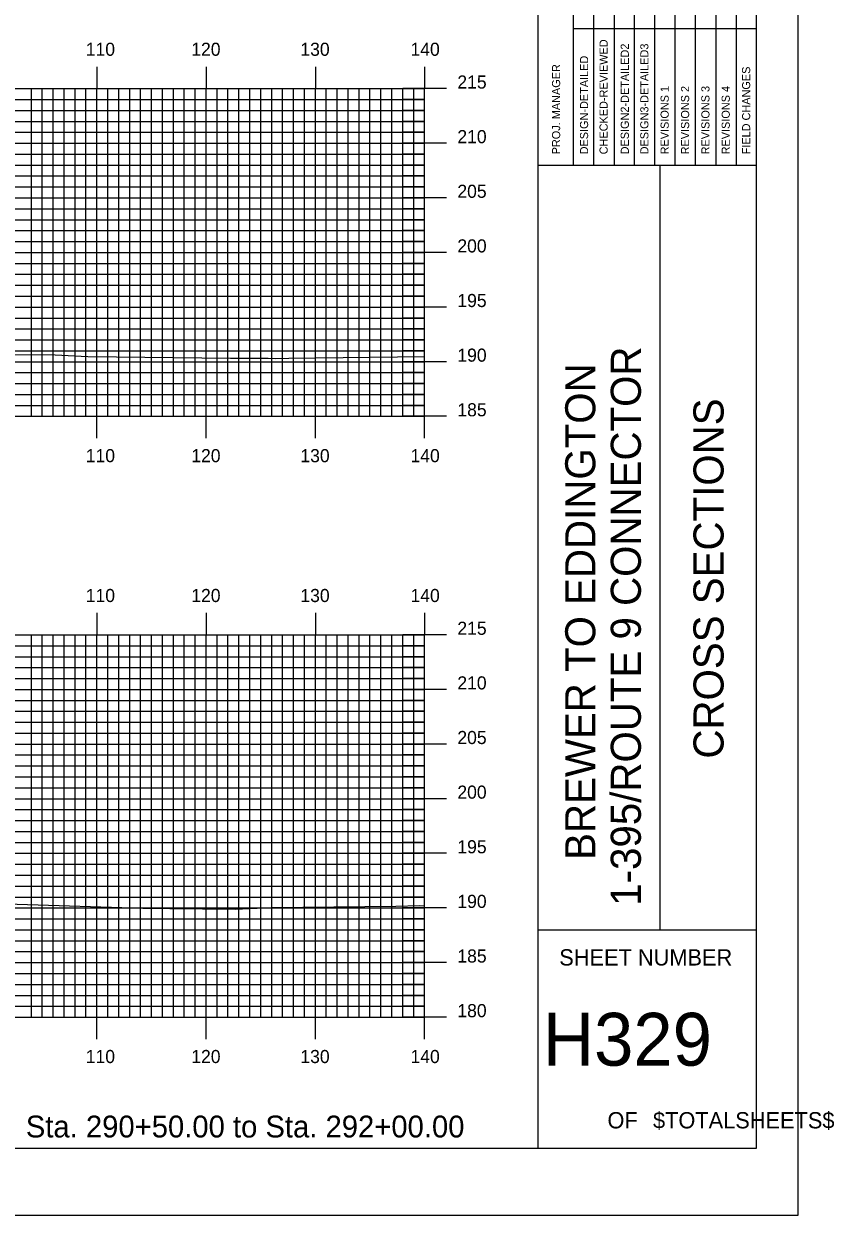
# Model space of a CAD drawing. Extents: x 1813735 to 1814078, y 442591 to 442811.
# Drawn here: x 1814003.8 to 1814078, y 442590.5 to 442699.6 of the extents above; entities that cross this region are included whole.
import ezdxf

# ---------------------------------------------------------------- set-up
doc = ezdxf.new("R2010")
doc.units = 0
for name, color, linetype in [('BORDER', 7, 'Continuous'), ('H_V ANNOTATION', 7, 'Continuous'), ('MAJOR', 7, 'Continuous'), ('MINOR', 7, 'Continuous'), ('PLOT BOUNDARY', 7, 'Continuous'), ('S_Roadway_Centerline', 7, 'Continuous')]:
    doc.layers.add(name, color=color, linetype=linetype)

msp = doc.modelspace()

# ---------------------------------------------------------------- linework, layer by layer
at = {"layer": 'BORDER'}
for p, q in [((1814050.88, 442596.67), (1814050.88, 442806.67)), ((1814050.88, 442686.67), (1814070.88, 442686.67)), ((1814062.06, 442616.67), (1814062.06, 442686.67)), ((1814050.88, 442616.67), (1814070.88, 442616.67))]:
    msp.add_line(p, q, dxfattribs=at)
msp.add_lwpolyline([(1813750.88, 442596.67), (1814070.88, 442596.67), (1814070.88, 442806.67), (1813750.88, 442806.67)], close=True, dxfattribs=at)
for points in [[(1814055.98, 442686.68), (1814055.98, 442721.67)], [(1814057.84, 442721.67), (1814057.84, 442686.68)], [(1814059.7, 442686.68), (1814059.7, 442721.67)], [(1814061.57, 442686.68), (1814061.57, 442721.67)], [(1814063.43, 442686.68), (1814063.43, 442721.67)], [(1814065.29, 442686.68), (1814065.29, 442721.67)], [(1814067.16, 442686.68), (1814067.16, 442721.67)], [(1814069.02, 442686.68), (1814069.02, 442721.67)], [(1814054.11, 442686.68), (1814054.11, 442720.26)], [(1814054.11, 442699.17), (1814070.88, 442699.17)]]:
    msp.add_lwpolyline(points, dxfattribs=at)
at = {"layer": 'MAJOR'}
for p, q in [((1814010.48, 442695.67), (1814010.48, 442693.67)), ((1814020.48, 442695.67), (1814020.48, 442693.67)), ((1814030.48, 442695.67), (1814030.48, 442693.67)), ((1814040.48, 442695.67), (1814040.48, 442693.67)), ((1813760.48, 442693.67), (1814040.48, 442693.67)), ((1813760.48, 442693.67), (1814040.48, 442693.67)), ((1814010.48, 442663.67), (1814010.48, 442693.67)), ((1814020.48, 442663.67), (1814020.48, 442693.67)), ((1814030.48, 442663.67), (1814030.48, 442693.67)), ((1814042.49, 442693.67), (1814038.48, 442693.67)), ((1814040.48, 442663.67), (1814040.48, 442693.67)), ((1814040.48, 442663.67), (1814040.48, 442693.67)), ((1813760.48, 442688.67), (1814040.48, 442688.67)), ((1814042.49, 442688.67), (1814038.48, 442688.67)), ((1813760.48, 442683.67), (1814040.48, 442683.67)), ((1814042.49, 442683.67), (1814038.48, 442683.67)), ((1813760.48, 442678.67), (1814040.48, 442678.67)), ((1814042.49, 442678.67), (1814038.48, 442678.67)), ((1813760.48, 442673.67), (1814040.48, 442673.67)), ((1814042.49, 442673.67), (1814038.48, 442673.67)), ((1813760.48, 442668.67), (1814040.48, 442668.67)), ((1814042.49, 442668.67), (1814038.48, 442668.67)), ((1813760.48, 442663.67), (1814040.48, 442663.67)), ((1813760.48, 442663.67), (1814040.48, 442663.67)), ((1814010.48, 442661.66), (1814010.48, 442663.67)), ((1814020.48, 442661.66), (1814020.48, 442663.67)), ((1814030.48, 442661.66), (1814030.48, 442663.67)), ((1814042.49, 442663.67), (1814038.48, 442663.67)), ((1814040.48, 442661.66), (1814040.48, 442663.67)), ((1814010.48, 442645.67), (1814010.48, 442643.67)), ((1814020.48, 442645.67), (1814020.48, 442643.67)), ((1814030.48, 442645.67), (1814030.48, 442643.67)), ((1814040.48, 442645.67), (1814040.48, 442643.67)), ((1813760.48, 442643.67), (1814040.48, 442643.67)), ((1813760.48, 442643.67), (1814040.48, 442643.67)), ((1814010.48, 442608.67), (1814010.48, 442643.67)), ((1814020.48, 442608.67), (1814020.48, 442643.67)), ((1814030.48, 442608.67), (1814030.48, 442643.67)), ((1814042.49, 442643.67), (1814038.48, 442643.67)), ((1814040.48, 442608.67), (1814040.48, 442643.67)), ((1814040.48, 442608.67), (1814040.48, 442643.67)), ((1813760.48, 442638.67), (1814040.48, 442638.67)), ((1814042.49, 442638.67), (1814038.48, 442638.67)), ((1813760.48, 442633.67), (1814040.48, 442633.67)), ((1814042.49, 442633.67), (1814038.48, 442633.67)), ((1813760.48, 442628.67), (1814040.48, 442628.67)), ((1814042.49, 442628.67), (1814038.48, 442628.67)), ((1813760.48, 442623.67), (1814040.48, 442623.67)), ((1814042.49, 442623.67), (1814038.48, 442623.67)), ((1813760.48, 442618.67), (1814040.48, 442618.67)), ((1814042.49, 442618.67), (1814038.48, 442618.67)), ((1813760.48, 442613.67), (1814040.48, 442613.67)), ((1814042.49, 442613.67), (1814038.48, 442613.67)), ((1813760.48, 442608.67), (1814040.48, 442608.67)), ((1813760.48, 442608.67), (1814040.48, 442608.67)), ((1814010.48, 442606.66), (1814010.48, 442608.67)), ((1814020.48, 442606.66), (1814020.48, 442608.67)), ((1814030.48, 442606.66), (1814030.48, 442608.67)), ((1814042.49, 442608.67), (1814038.48, 442608.67)), ((1814040.48, 442606.66), (1814040.48, 442608.67))]:
    msp.add_line(p, q, dxfattribs=at)
at = {"layer": 'MINOR'}
for p, q in [((1814004.48, 442663.67), (1814004.48, 442693.67)), ((1814005.48, 442663.67), (1814005.48, 442693.67)), ((1814006.48, 442663.67), (1814006.48, 442693.67)), ((1814007.48, 442663.67), (1814007.48, 442693.67)), ((1814008.48, 442663.67), (1814008.48, 442693.67)), ((1814009.48, 442663.67), (1814009.48, 442693.67)), ((1814011.48, 442663.67), (1814011.48, 442693.67)), ((1814012.48, 442663.67), (1814012.48, 442693.67)), ((1814013.48, 442663.67), (1814013.48, 442693.67)), ((1814014.48, 442663.67), (1814014.48, 442693.67)), ((1814015.48, 442663.67), (1814015.48, 442693.67)), ((1814016.48, 442663.67), (1814016.48, 442693.67)), ((1814017.48, 442663.67), (1814017.48, 442693.67)), ((1814018.48, 442663.67), (1814018.48, 442693.67)), ((1814019.48, 442663.67), (1814019.48, 442693.67)), ((1814021.48, 442663.67), (1814021.48, 442693.67)), ((1814022.48, 442663.67), (1814022.48, 442693.67)), ((1814023.48, 442663.67), (1814023.48, 442693.67)), ((1814024.48, 442663.67), (1814024.48, 442693.67)), ((1814025.48, 442663.67), (1814025.48, 442693.67)), ((1814026.48, 442663.67), (1814026.48, 442693.67)), ((1814027.48, 442663.67), (1814027.48, 442693.67)), ((1814028.48, 442663.67), (1814028.48, 442693.67)), ((1814029.48, 442663.67), (1814029.48, 442693.67)), ((1814031.48, 442663.67), (1814031.48, 442693.67)), ((1814032.48, 442663.67), (1814032.48, 442693.67)), ((1814033.48, 442663.67), (1814033.48, 442693.67)), ((1814034.48, 442663.67), (1814034.48, 442693.67)), ((1814035.48, 442663.67), (1814035.48, 442693.67)), ((1814036.48, 442663.67), (1814036.48, 442693.67)), ((1814037.48, 442663.67), (1814037.48, 442693.67)), ((1814038.48, 442663.67), (1814038.48, 442693.67)), ((1814039.48, 442663.67), (1814039.48, 442693.67)), ((1813760.48, 442692.67), (1814040.48, 442692.67)), ((1813760.48, 442691.67), (1814040.48, 442691.67)), ((1814040.48, 442692.67), (1814038.48, 442692.67)), ((1814040.48, 442691.67), (1814038.48, 442691.67)), ((1813760.48, 442690.67), (1814040.48, 442690.67)), ((1814040.48, 442690.67), (1814038.48, 442690.67)), ((1813760.48, 442689.67), (1814040.48, 442689.67)), ((1814040.48, 442689.67), (1814038.48, 442689.67)), ((1813760.48, 442687.67), (1814040.48, 442687.67)), ((1814040.48, 442687.67), (1814038.48, 442687.67)), ((1813760.48, 442686.67), (1814040.48, 442686.67)), ((1814040.48, 442686.67), (1814038.48, 442686.67)), ((1813760.48, 442685.67), (1814040.48, 442685.67)), ((1814040.48, 442685.67), (1814038.48, 442685.67)), ((1813760.48, 442684.67), (1814040.48, 442684.67)), ((1814040.48, 442684.67), (1814038.48, 442684.67)), ((1813760.48, 442682.67), (1814040.48, 442682.67)), ((1814040.48, 442682.67), (1814038.48, 442682.67)), ((1813760.48, 442681.67), (1814040.48, 442681.67)), ((1814040.48, 442681.67), (1814038.48, 442681.67)), ((1813760.48, 442680.67), (1814040.48, 442680.67)), ((1813760.48, 442679.67), (1814040.48, 442679.67)), ((1814040.48, 442680.67), (1814038.48, 442680.67)), ((1814040.48, 442679.67), (1814038.48, 442679.67)), ((1813760.48, 442677.67), (1814040.48, 442677.67)), ((1814040.48, 442677.67), (1814038.48, 442677.67)), ((1813760.48, 442676.67), (1814040.48, 442676.67)), ((1814040.48, 442676.67), (1814038.48, 442676.67)), ((1813760.48, 442675.67), (1814040.48, 442675.67)), ((1814040.48, 442675.67), (1814038.48, 442675.67)), ((1813760.48, 442674.67), (1814040.48, 442674.67)), ((1814040.48, 442674.67), (1814038.48, 442674.67)), ((1813760.48, 442672.67), (1814040.48, 442672.67)), ((1814040.48, 442672.67), (1814038.48, 442672.67)), ((1813760.48, 442671.67), (1814040.48, 442671.67)), ((1814040.48, 442671.67), (1814038.48, 442671.67)), ((1813760.48, 442670.67), (1814040.48, 442670.67)), ((1814040.48, 442670.67), (1814038.48, 442670.67)), ((1813760.48, 442669.67), (1814040.48, 442669.67)), ((1814040.48, 442669.67), (1814038.48, 442669.67)), ((1813760.48, 442667.67), (1814040.48, 442667.67)), ((1814040.48, 442667.67), (1814038.48, 442667.67)), ((1813760.48, 442666.67), (1814040.48, 442666.67)), ((1814040.48, 442666.67), (1814038.48, 442666.67)), ((1813760.48, 442665.67), (1814040.48, 442665.67)), ((1814040.48, 442665.67), (1814038.48, 442665.67)), ((1813760.48, 442664.67), (1814040.48, 442664.67)), ((1814040.48, 442664.67), (1814038.48, 442664.67)), ((1814004.48, 442608.67), (1814004.48, 442643.67)), ((1814005.48, 442608.67), (1814005.48, 442643.67)), ((1814006.48, 442608.67), (1814006.48, 442643.67)), ((1814007.48, 442608.67), (1814007.48, 442643.67)), ((1814008.48, 442608.67), (1814008.48, 442643.67)), ((1814009.48, 442608.67), (1814009.48, 442643.67)), ((1814011.48, 442608.67), (1814011.48, 442643.67)), ((1814012.48, 442608.67), (1814012.48, 442643.67)), ((1814013.48, 442608.67), (1814013.48, 442643.67)), ((1814014.48, 442608.67), (1814014.48, 442643.67)), ((1814015.48, 442608.67), (1814015.48, 442643.67)), ((1814016.48, 442608.67), (1814016.48, 442643.67)), ((1814017.48, 442608.67), (1814017.48, 442643.67)), ((1814018.48, 442608.67), (1814018.48, 442643.67)), ((1814019.48, 442608.67), (1814019.48, 442643.67)), ((1814021.48, 442608.67), (1814021.48, 442643.67)), ((1814022.48, 442608.67), (1814022.48, 442643.67)), ((1814023.48, 442608.67), (1814023.48, 442643.67)), ((1814024.48, 442608.67), (1814024.48, 442643.67)), ((1814025.48, 442608.67), (1814025.48, 442643.67)), ((1814026.48, 442608.67), (1814026.48, 442643.67)), ((1814027.48, 442608.67), (1814027.48, 442643.67)), ((1814028.48, 442608.67), (1814028.48, 442643.67)), ((1814029.48, 442608.67), (1814029.48, 442643.67)), ((1814031.48, 442608.67), (1814031.48, 442643.67)), ((1814032.48, 442608.67), (1814032.48, 442643.67)), ((1814033.48, 442608.67), (1814033.48, 442643.67)), ((1814034.48, 442608.67), (1814034.48, 442643.67)), ((1814035.48, 442608.67), (1814035.48, 442643.67)), ((1814036.48, 442608.67), (1814036.48, 442643.67)), ((1814037.48, 442608.67), (1814037.48, 442643.67)), ((1814038.48, 442608.67), (1814038.48, 442643.67)), ((1814039.48, 442608.67), (1814039.48, 442643.67)), ((1813760.48, 442642.67), (1814040.48, 442642.67)), ((1814040.48, 442642.67), (1814038.48, 442642.67)), ((1813760.48, 442641.67), (1814040.48, 442641.67)), ((1814040.48, 442641.67), (1814038.48, 442641.67)), ((1813760.48, 442640.67), (1814040.48, 442640.67)), ((1814040.48, 442640.67), (1814038.48, 442640.67)), ((1813760.48, 442639.67), (1814040.48, 442639.67)), ((1814040.48, 442639.67), (1814038.48, 442639.67)), ((1813760.48, 442637.67), (1814040.48, 442637.67)), ((1814040.48, 442637.67), (1814038.48, 442637.67)), ((1813760.48, 442636.67), (1814040.48, 442636.67)), ((1814040.48, 442636.67), (1814038.48, 442636.67)), ((1813760.48, 442635.67), (1814040.48, 442635.67)), ((1814040.48, 442635.67), (1814038.48, 442635.67)), ((1813760.48, 442634.67), (1814040.48, 442634.67)), ((1814040.48, 442634.67), (1814038.48, 442634.67)), ((1813760.48, 442632.67), (1814040.48, 442632.67)), ((1814040.48, 442632.67), (1814038.48, 442632.67)), ((1813760.48, 442631.67), (1814040.48, 442631.67)), ((1813760.48, 442630.67), (1814040.48, 442630.67)), ((1814040.48, 442631.67), (1814038.48, 442631.67)), ((1814040.48, 442630.67), (1814038.48, 442630.67)), ((1813760.48, 442629.67), (1814040.48, 442629.67)), ((1814040.48, 442629.67), (1814038.48, 442629.67)), ((1813760.48, 442627.67), (1814040.48, 442627.67)), ((1814040.48, 442627.67), (1814038.48, 442627.67)), ((1813760.48, 442626.67), (1814040.48, 442626.67)), ((1814040.48, 442626.67), (1814038.48, 442626.67)), ((1813760.48, 442625.67), (1814040.48, 442625.67)), ((1814040.48, 442625.67), (1814038.48, 442625.67)), ((1813760.48, 442624.67), (1814040.48, 442624.67)), ((1814040.48, 442624.67), (1814038.48, 442624.67)), ((1813760.48, 442622.67), (1814040.48, 442622.67)), ((1814040.48, 442622.67), (1814038.48, 442622.67)), ((1813760.48, 442621.67), (1814040.48, 442621.67)), ((1814040.48, 442621.67), (1814038.48, 442621.67)), ((1813760.48, 442620.67), (1814040.48, 442620.67)), ((1814040.48, 442620.67), (1814038.48, 442620.67)), ((1813760.48, 442619.67), (1814040.48, 442619.67)), ((1814040.48, 442619.67), (1814038.48, 442619.67)), ((1813760.48, 442617.67), (1814040.48, 442617.67)), ((1814040.48, 442617.67), (1814038.48, 442617.67)), ((1813760.48, 442616.67), (1814040.48, 442616.67)), ((1814040.48, 442616.67), (1814038.48, 442616.67)), ((1813760.48, 442615.67), (1814040.48, 442615.67)), ((1814040.48, 442615.67), (1814038.48, 442615.67)), ((1813760.48, 442614.67), (1814040.48, 442614.67)), ((1814040.48, 442614.67), (1814038.48, 442614.67)), ((1813760.48, 442612.67), (1814040.48, 442612.67)), ((1814040.48, 442612.67), (1814038.48, 442612.67)), ((1813760.48, 442611.67), (1814040.48, 442611.67)), ((1814040.48, 442611.67), (1814038.48, 442611.67)), ((1813760.48, 442610.67), (1814040.48, 442610.67)), ((1814040.48, 442610.67), (1814038.48, 442610.67)), ((1813760.48, 442609.67), (1814040.48, 442609.67)), ((1814040.48, 442609.67), (1814038.48, 442609.67))]:
    msp.add_line(p, q, dxfattribs=at)
at = {"layer": 'PLOT BOUNDARY'}
msp.add_lwpolyline([(1813734.69, 442590.55), (1814074.69, 442590.55), (1814074.69, 442810.55), (1813734.69, 442810.55)], close=True, dxfattribs=at)
at = {"layer": 'S_Roadway_Centerline'}
for points in [[(1813959.72, 442671.18), (1813974.92, 442669.72), (1813976.9, 442669.58), (1813978.3, 442669.52), (1813987.04, 442669.42), (1814006.66, 442669.31), (1814009.65, 442669.15), (1814022.72, 442668.98), (1814026.17, 442668.98), (1814026.81, 442668.96), (1814028.04, 442669), (1814040.48, 442669.14)], [(1813957, 442620), (1813979.82, 442619.26), (1813985.27, 442619.1), (1813986.92, 442619.05), (1813987.44, 442619.04), (1814001.85, 442619.04), (1814003.18, 442619.02), (1814014.69, 442618.66), (1814017.17, 442618.61), (1814023.13, 442618.56), (1814026.49, 442618.71), (1814037.85, 442618.82), (1814040, 442618.88), (1814040.48, 442618.86)]]:
    msp.add_lwpolyline(points, dxfattribs=at)

# ---------------------------------------------------------------- texts
at = {"layer": 'BORDER'}
for s, height, p in [('CHECKED-REVIEWED', 0.7455, (1814057.24, 442687.65)), ('DESIGN2-DETAILED2', 0.7455, (1814059.18, 442687.65)), ('DESIGN3-DETAILED3', 0.7455, (1814060.97, 442687.65)), ('DESIGN-DETAILED', 0.7455, (1814055.45, 442687.65)), ('PROJ. MANAGER', 0.7455, (1814052.89, 442687.65)), ('FIELD CHANGES', 0.7455, (1814070.29, 442687.65)), ('REVISIONS 1', 0.7455, (1814062.83, 442687.65)), ('REVISIONS 2', 0.7455, (1814064.7, 442687.65)), ('REVISIONS 3', 0.7455, (1814066.56, 442687.65)), ('REVISIONS 4', 0.7455, (1814068.42, 442687.65)), ('1-395/ROUTE 9 CONNECTOR', 2.7557, (1814060.28, 442618.87)), ('BREWER TO EDDINGTON', 2.7557, (1814056.11, 442623.07)), ('CROSS SECTIONS', 2.7557, (1814067.85, 442632.34))]:
    msp.add_text(s, height=height, rotation=90, dxfattribs=at).set_placement(p)
for s, height, p in [('SHEET NUMBER', 1.4905, (1814052.81, 442613.4)), ('H329', 4.839, (1814051.32, 442604.23)), ('$TOTALSHEETS$', 1.4905, (1814061.39, 442598.49)), ('OF', 1.491, (1814057.22, 442598.49))]:
    msp.add_text(s, height=height, dxfattribs=at).set_placement(p)
at = {"layer": 'H_V ANNOTATION'}
for s, height, p in [('110', 1.2, (1814009.46, 442696.67)), ('120', 1.2, (1814019.12, 442696.67)), ('130', 1.2, (1814029.11, 442696.67)), ('140', 1.2, (1814039.19, 442696.67)), ('215', 1.2, (1814043.48, 442693.67)), ('210', 1.2, (1814043.48, 442688.67)), ('205', 1.2, (1814043.48, 442683.67)), ('200', 1.2, (1814043.48, 442678.67)), ('195', 1.2, (1814043.48, 442673.67)), ('190', 1.2, (1814043.48, 442668.67)), ('185', 1.2, (1814043.48, 442663.67)), ('110', 1.2, (1814009.46, 442659.47)), ('120', 1.2, (1814019.12, 442659.47)), ('130', 1.2, (1814029.11, 442659.47)), ('140', 1.2, (1814039.19, 442659.47)), ('110', 1.2, (1814009.46, 442646.67)), ('120', 1.2, (1814019.12, 442646.67)), ('130', 1.2, (1814029.11, 442646.67)), ('140', 1.2, (1814039.19, 442646.67)), ('215', 1.2, (1814043.48, 442643.67)), ('210', 1.2, (1814043.48, 442638.67)), ('205', 1.2, (1814043.48, 442633.67)), ('200', 1.2, (1814043.48, 442628.67)), ('195', 1.2, (1814043.48, 442623.67)), ('190', 1.2, (1814043.48, 442618.67)), ('185', 1.2, (1814043.48, 442613.67)), ('180', 1.2, (1814043.48, 442608.67)), ('110', 1.2, (1814009.46, 442604.47)), ('120', 1.2, (1814019.12, 442604.47)), ('130', 1.2, (1814029.11, 442604.47)), ('140', 1.2, (1814039.19, 442604.47)), ('Sta. 290+50.00 to Sta. 292+00.00', 2.0004, (1814003.97, 442597.66))]:
    msp.add_text(s, height=height, dxfattribs=at).set_placement(p)

doc.saveas('drawing.dxf')
